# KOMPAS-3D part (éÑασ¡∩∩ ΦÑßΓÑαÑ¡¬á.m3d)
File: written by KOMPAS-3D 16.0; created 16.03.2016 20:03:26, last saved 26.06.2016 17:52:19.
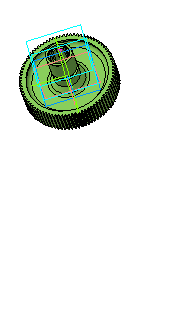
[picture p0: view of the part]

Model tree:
1. Эскиз:1
2. Операция выдавливания:1
     Расстояние 1 = 21
3. Эскиз:2
4. Вырезать элемент выдавливания:1
     Расстояние 1 = 6
5. Скругление:1
     Радиус = 2.5
6. Эскиз:3
7. Вырезать элемент выдавливания:2
     Расстояние 1 = 6
8. Уклон:1
     Угол уклона = 41
9. Скругление:2
     Радиус = 4
10. Эскиз:4
11. Операция выдавливания:2
     Расстояние 1 = 18; На расстояние 1 = 18
12. Эскиз:7
13. Вырезать элемент выдавливания:4
     Расстояние 1 = 6
14. Скругление:3
     Радиус = 4
15. Эскиз:8
16. Операция выдавливания:4
     Расстояние 1 = 6; На расстояние 1 = 18
17. Уклон:2
     Угол уклона = 41
18. Скругление:4
     Радиус = 4
19. Операция выдавливания:5
     Расстояние 1 = 35; На расстояние 1 = 18
20. Смещенная плоскость:1
     Расстояние = 10
21. Эскиз:9
22. Вырезать элемент выдавливания:5
     Расстояние 1 = 4
23. Эскиз:10
24. Вырезать элемент выдавливания:6
     Расстояние 1 = 35
25. Эскиз:11
26. Вырезать элемент выдавливания:7
     Расстояние 1 = 4
27. Эскиз:12
28. Вырезать элемент выдавливания:9
     Расстояние 1 = 14
29. Массив по концентрической сетке:1  (with: Вырезать элемент выдавливания:9, Эскиз:12)  (8 pattern instances)
     Геометрический массив = 7; Шаг 2 = 360
30. Эскиз:13
31. Смещенная плоскость:2
     Расстояние = 32
32. Эскиз:14
33. Вырезать элемент выдавливания:11
     Расстояние 1 = 0.5
34. Вырезать элемент выдавливания:12
     Расстояние 1 = 23
35. Массив по концентрической сетке:5  (with: Вырезать элемент выдавливания:12, Эскиз:13)  (86 pattern instances)
     Геометрический массив = 85; Шаг 2 = 360

Referenced files in E:\мои доки\: ВЫАфа.png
